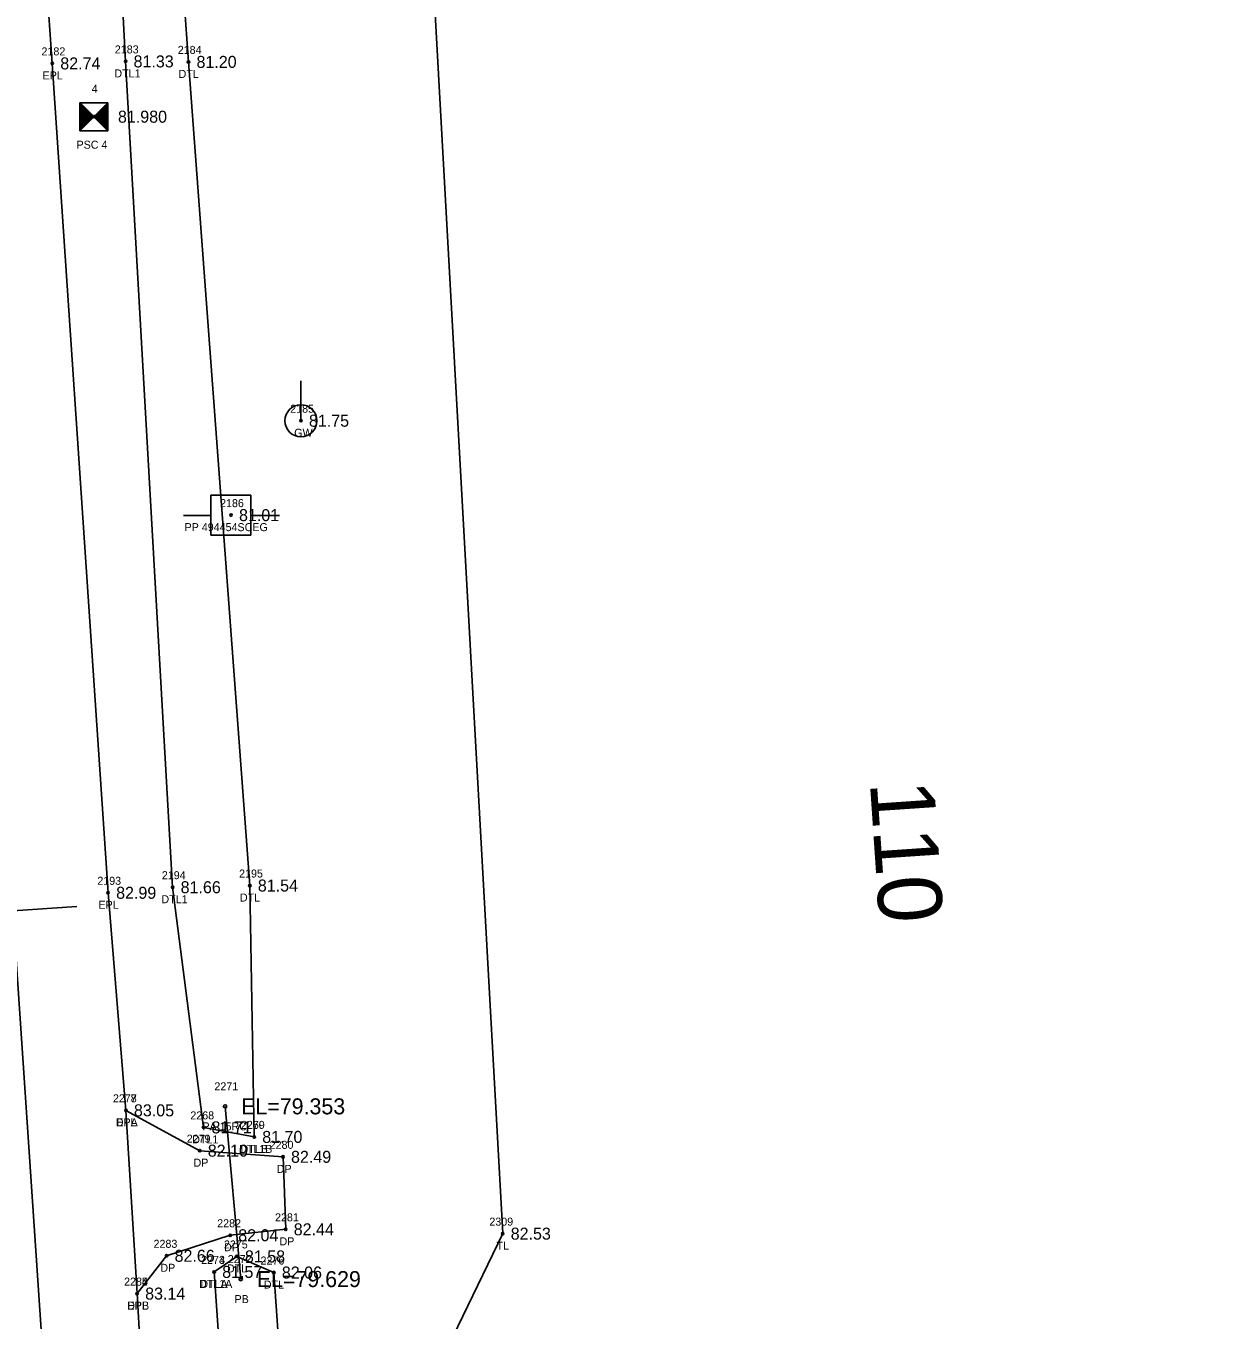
# Model space of a CAD drawing. Extents: x 2139392 to 2143384, y 505395 to 510520.
# Drawn here: x 2140601.5 to 2140750.5, y 507174.1 to 507335.9 of the extents above; entities that cross this region are included whole.
import ezdxf

# ---------------------------------------------------------------- set-up
doc = ezdxf.new("R2010")
doc.units = 0
for name, color, linetype in [('RD_EX_DR_Pipe', 7, 'Continuous'), ('RD_EX_DR_Pipe_txCode', 7, 'Continuous'), ('RD_EX_Driveway', 7, 'Continuous'), ('RD_EX_Driveway_txCode', 7, 'Continuous'), ('RD_EX_H2O', 7, 'Continuous'), ('RD_EX_H2O_txCode', 7, 'Continuous'), ('RD_EX_Road', 7, 'Continuous'), ('RD_EX_Road_txCode', 7, 'Continuous'), ('RD_EX_TX_Driveway_ELEV', 7, 'Continuous'), ('RD_EX_TX_H2O_ELEV', 7, 'Continuous'), ('RD_EX_TX_Road_ELEV', 7, 'Continuous'), ('RD_EX_TX_UT_ELEV', 7, 'Continuous'), ('RD_EX_TX_VEG_ELEV', 7, 'Continuous'), ('RD_EX_UT', 7, 'Continuous'), ('RD_EX_UT_txCode', 7, 'Continuous'), ('RD_EX_VEG', 7, 'Continuous'), ('RD_EX_VEG_txCode', 7, 'Continuous'), ('RD_HC_Cl', 7, 'Continuous'), ('RD_HC_Data_Tic', 7, 'Continuous'), ('RD_HC_Survey', 7, 'Continuous'), ('RD_HC_Survey_ELEV', 7, 'Continuous'), ('RD_HC_TX_Sta50', 7, 'Continuous'), ('RD_HC_txCode', 7, 'Continuous'), ('RD_SMD_Locator', 7, 'Continuous'), ('RD_TX_Pipe_ElevEX', 7, 'Continuous')]:
    doc.layers.add(name, color=color, linetype=linetype)

msp = doc.modelspace()

# ---------------------------------------------------------------- linework, layer by layer
at = {"layer": 'RD_EX_DR_Pipe'}
msp.add_line((2140626.44, 507200.86), (2140628.4, 507179.27), dxfattribs=at)
at = {"layer": 'RD_EX_Driveway'}
msp.add_lwpolyline([(2140614.04, 507200.36), (2140623.27, 507195.32), (2140633.68, 507194.55), (2140634.02, 507185.49), (2140627.08, 507184.75), (2140619.12, 507182.18), (2140615.44, 507177.46)], dxfattribs=at)
at = {"layer": 'RD_EX_H2O'}
msp.add_line((2140625.07, 507180.17), (2140625.92, 507167.91), dxfattribs=at)
for points in [[(2140603.99, 507551.21), (2140601.87, 507547.52), (2140605.21, 507495.06), (2140608.3, 507440.3), (2140613.99, 507331.46), (2140619.88, 507228.25), (2140623.74, 507198.23), (2140630.08, 507197.04)], [(2140603.99, 507551.21), (2140608.04, 507548.03), (2140611.33, 507495.05), (2140614.04, 507440.89), (2140621.86, 507331.4), (2140629.53, 507228.46), (2140630.08, 507197.04)], [(2140625.07, 507180.17), (2140627.92, 507182.1), (2140632.53, 507180.09), (2140633.39, 507167.5), (2140629.4, 507165.09), (2140625.92, 507167.91)]]:
    msp.add_lwpolyline(points, dxfattribs=at)
at = {"layer": 'RD_EX_Road'}
msp.add_lwpolyline([(2140583.43, 507730.59), (2140583.94, 507673.5), (2140583.85, 507666.58), (2140586.13, 507612.82), (2140586.39, 507606.18), (2140590.25, 507541.6), (2140593.48, 507494.33), (2140597.22, 507439.46), (2140604.83, 507331.21), (2140611.81, 507227.55), (2140614.04, 507200.36), (2140615.44, 507177.46), (2140615.82, 507170.81), (2140617.54, 507144.2), (2140618.8, 507126.38), (2140619.22, 507121.84), (2140620.89, 507096.21), (2140626.38, 507013.96)], dxfattribs=at)
at = {"layer": 'RD_EX_UT'}
for p, q in [((2140635.92, 507286.55), (2140635.92, 507291.55)), ((2140629.67, 507277.25), (2140624.67, 507277.25)), ((2140624.67, 507277.25), (2140624.67, 507272.25)), ((2140629.67, 507272.25), (2140629.67, 507277.25)), ((2140621.24, 507274.69), (2140624.71, 507274.69)), ((2140629.6, 507274.69), (2140633.24, 507274.69)), ((2140624.67, 507272.25), (2140629.67, 507272.25))]:
    msp.add_line(p, q, dxfattribs=at)
msp.add_circle((2140635.92, 507286.55), 2, dxfattribs=at)
at = {"layer": 'RD_EX_VEG'}
msp.add_lwpolyline([(2140701.46, 507529.17), (2140641.02, 507547.61), (2140661.15, 507184.95), (2140652.41, 507166.87), (2140661.6, 507156.19), (2140726.62, 507140.25), (2140736.68, 507079.23), (2140750.48, 507072.39)], dxfattribs=at)
at = {"layer": 'RD_HC_Cl'}
msp.add_line((2140574.74, 507595.12), (2140664.08, 506281.81), dxfattribs=at)
at = {"layer": 'RD_HC_Data_Tic'}
msp.add_line((2140599.9, 507225.31), (2140607.88, 507225.85), dxfattribs=at)
at = {"layer": 'RD_HC_Survey'}
for p, q in [((2140608.29, 507326.3), (2140611.79, 507322.8)), ((2140611.79, 507326.3), (2140608.29, 507322.8)), ((2140608.31, 507326.28), (2140608.31, 507322.83)), ((2140608.34, 507326.25), (2140608.34, 507322.85)), ((2140608.36, 507326.23), (2140608.36, 507322.88)), ((2140608.39, 507326.2), (2140608.39, 507322.9)), ((2140608.41, 507326.18), (2140608.41, 507322.93)), ((2140608.43, 507326.15), (2140608.43, 507322.95)), ((2140608.46, 507326.13), (2140608.46, 507322.97)), ((2140608.48, 507326.1), (2140608.48, 507323)), ((2140608.51, 507326.08), (2140608.51, 507323.02)), ((2140608.53, 507326.05), (2140608.53, 507323.05)), ((2140608.56, 507326.03), (2140608.56, 507323.07)), ((2140608.58, 507326), (2140608.58, 507323.1)), ((2140608.61, 507325.98), (2140608.61, 507323.12)), ((2140608.63, 507325.96), (2140608.63, 507323.15)), ((2140608.66, 507325.93), (2140608.66, 507323.17)), ((2140608.68, 507325.91), (2140608.68, 507323.2)), ((2140608.71, 507325.88), (2140608.71, 507323.22)), ((2140608.73, 507325.86), (2140608.73, 507323.25)), ((2140608.76, 507325.83), (2140608.76, 507323.27)), ((2140608.78, 507325.81), (2140608.78, 507323.3)), ((2140608.81, 507325.78), (2140608.81, 507323.32)), ((2140608.83, 507325.76), (2140608.83, 507323.35)), ((2140608.86, 507325.73), (2140608.86, 507323.37)), ((2140608.88, 507325.71), (2140608.88, 507323.4)), ((2140608.91, 507325.68), (2140608.91, 507323.42)), ((2140608.93, 507325.66), (2140608.93, 507323.45)), ((2140608.95, 507325.63), (2140608.95, 507323.47)), ((2140608.98, 507325.61), (2140608.98, 507323.49)), ((2140609, 507325.58), (2140609, 507323.52)), ((2140609.03, 507325.56), (2140609.03, 507323.54)), ((2140609.05, 507325.53), (2140609.05, 507323.57)), ((2140609.08, 507325.51), (2140609.08, 507323.59)), ((2140609.1, 507325.48), (2140609.1, 507323.62)), ((2140609.13, 507325.46), (2140609.13, 507323.64)), ((2140609.15, 507325.44), (2140609.15, 507323.67)), ((2140609.18, 507325.41), (2140609.18, 507323.69)), ((2140609.2, 507325.39), (2140609.2, 507323.72)), ((2140609.23, 507325.36), (2140609.23, 507323.74)), ((2140609.25, 507325.34), (2140609.25, 507323.77)), ((2140609.28, 507325.31), (2140609.28, 507323.79)), ((2140609.3, 507325.29), (2140609.3, 507323.82)), ((2140609.33, 507325.26), (2140609.33, 507323.84)), ((2140609.35, 507325.24), (2140609.35, 507323.87)), ((2140609.38, 507325.21), (2140609.38, 507323.89)), ((2140609.4, 507325.19), (2140609.4, 507323.92)), ((2140609.42, 507325.16), (2140609.42, 507323.94)), ((2140609.45, 507325.14), (2140609.45, 507323.96)), ((2140609.47, 507325.11), (2140609.47, 507323.99)), ((2140609.5, 507325.09), (2140609.5, 507324.01)), ((2140609.52, 507325.06), (2140609.52, 507324.04)), ((2140609.55, 507325.04), (2140609.55, 507324.06)), ((2140609.57, 507325.01), (2140609.57, 507324.09)), ((2140609.6, 507324.99), (2140609.6, 507324.11)), ((2140609.62, 507324.97), (2140609.62, 507324.14)), ((2140609.65, 507324.94), (2140609.65, 507324.16)), ((2140609.67, 507324.92), (2140609.67, 507324.19)), ((2140609.7, 507324.89), (2140609.7, 507324.21)), ((2140609.72, 507324.87), (2140609.72, 507324.24)), ((2140610.35, 507324.87), (2140610.35, 507324.24)), ((2140610.38, 507324.89), (2140610.38, 507324.21)), ((2140610.4, 507324.92), (2140610.4, 507324.19)), ((2140610.43, 507324.94), (2140610.43, 507324.16)), ((2140610.45, 507324.97), (2140610.45, 507324.14)), ((2140610.47, 507324.99), (2140610.47, 507324.11)), ((2140610.5, 507325.01), (2140610.5, 507324.09)), ((2140610.52, 507325.04), (2140610.52, 507324.06)), ((2140610.55, 507325.06), (2140610.55, 507324.04)), ((2140610.57, 507325.09), (2140610.57, 507324.01)), ((2140610.6, 507325.11), (2140610.6, 507323.99)), ((2140610.62, 507325.14), (2140610.62, 507323.96)), ((2140610.65, 507325.16), (2140610.65, 507323.94)), ((2140610.67, 507325.19), (2140610.67, 507323.92)), ((2140610.7, 507325.21), (2140610.7, 507323.89)), ((2140610.72, 507325.24), (2140610.72, 507323.87)), ((2140610.75, 507325.26), (2140610.75, 507323.84)), ((2140610.77, 507325.29), (2140610.77, 507323.82)), ((2140610.8, 507325.31), (2140610.8, 507323.79)), ((2140610.82, 507325.34), (2140610.82, 507323.77)), ((2140610.85, 507325.36), (2140610.85, 507323.74)), ((2140610.87, 507325.39), (2140610.87, 507323.72)), ((2140610.9, 507325.41), (2140610.9, 507323.69)), ((2140610.92, 507325.44), (2140610.92, 507323.67)), ((2140610.95, 507325.46), (2140610.95, 507323.64)), ((2140610.97, 507325.48), (2140610.97, 507323.62)), ((2140610.99, 507325.51), (2140610.99, 507323.59)), ((2140611.02, 507325.53), (2140611.02, 507323.57)), ((2140611.04, 507325.56), (2140611.04, 507323.54)), ((2140611.07, 507325.58), (2140611.07, 507323.52)), ((2140611.09, 507325.61), (2140611.09, 507323.49)), ((2140611.12, 507325.63), (2140611.12, 507323.47)), ((2140611.14, 507325.66), (2140611.14, 507323.45)), ((2140611.17, 507325.68), (2140611.17, 507323.42)), ((2140611.19, 507325.71), (2140611.19, 507323.4)), ((2140611.22, 507325.73), (2140611.22, 507323.37)), ((2140611.24, 507325.76), (2140611.24, 507323.35)), ((2140611.27, 507325.78), (2140611.27, 507323.32)), ((2140611.29, 507325.81), (2140611.29, 507323.3)), ((2140611.32, 507325.83), (2140611.32, 507323.27)), ((2140611.34, 507325.86), (2140611.34, 507323.25)), ((2140611.37, 507325.88), (2140611.37, 507323.22)), ((2140611.39, 507325.91), (2140611.39, 507323.2)), ((2140611.42, 507325.93), (2140611.42, 507323.17)), ((2140611.44, 507325.96), (2140611.44, 507323.15)), ((2140611.46, 507325.98), (2140611.46, 507323.12)), ((2140611.49, 507326), (2140611.49, 507323.1)), ((2140611.51, 507326.03), (2140611.51, 507323.07)), ((2140611.54, 507326.05), (2140611.54, 507323.05)), ((2140611.56, 507326.08), (2140611.56, 507323.02)), ((2140611.59, 507326.1), (2140611.59, 507323)), ((2140611.61, 507326.13), (2140611.61, 507322.97)), ((2140611.64, 507326.15), (2140611.64, 507322.95)), ((2140611.66, 507326.18), (2140611.66, 507322.93)), ((2140611.69, 507326.2), (2140611.69, 507322.9)), ((2140611.71, 507326.23), (2140611.71, 507322.88)), ((2140611.74, 507326.25), (2140611.74, 507322.85)), ((2140611.76, 507326.28), (2140611.76, 507322.83)), ((2140609.75, 507324.84), (2140609.75, 507324.26)), ((2140609.77, 507324.82), (2140609.77, 507324.29)), ((2140609.8, 507324.79), (2140609.8, 507324.31)), ((2140609.82, 507324.77), (2140609.82, 507324.34)), ((2140609.85, 507324.74), (2140609.85, 507324.36)), ((2140609.87, 507324.72), (2140609.87, 507324.39)), ((2140609.9, 507324.69), (2140609.9, 507324.41)), ((2140609.92, 507324.67), (2140609.92, 507324.44)), ((2140609.94, 507324.64), (2140609.94, 507324.46)), ((2140609.97, 507324.62), (2140609.97, 507324.48)), ((2140609.99, 507324.59), (2140609.99, 507324.51)), ((2140610.02, 507324.57), (2140610.02, 507324.53)), ((2140610.05, 507324.57), (2140610.05, 507324.53)), ((2140610.08, 507324.59), (2140610.08, 507324.51)), ((2140610.1, 507324.62), (2140610.1, 507324.48)), ((2140610.13, 507324.64), (2140610.13, 507324.46)), ((2140610.15, 507324.67), (2140610.15, 507324.44)), ((2140610.18, 507324.69), (2140610.18, 507324.41)), ((2140610.2, 507324.72), (2140610.2, 507324.39)), ((2140610.23, 507324.74), (2140610.23, 507324.36)), ((2140610.25, 507324.77), (2140610.25, 507324.34)), ((2140610.28, 507324.79), (2140610.28, 507324.31)), ((2140610.3, 507324.82), (2140610.3, 507324.29)), ((2140610.33, 507324.84), (2140610.33, 507324.26))]:
    msp.add_line(p, q, dxfattribs=at)
msp.add_lwpolyline([(2140611.79, 507326.3), (2140608.29, 507326.3), (2140608.29, 507322.8), (2140611.79, 507322.8)], close=True, dxfattribs=at)
at = {"layer": 'RD_SMD_Locator'}
for centre, radius in [((2140604.83, 507331.21), 0.15), ((2140613.99, 507331.46), 0.15), ((2140621.86, 507331.4), 0.15), ((2140610.04, 507324.55), 0.15), ((2140635.92, 507286.55), 0.15), ((2140627.18, 507274.75), 0.15), ((2140619.88, 507228.25), 0.15), ((2140629.53, 507228.46), 0.15), ((2140611.81, 507227.55), 0.15), ((2140614.04, 507200.36), 0.15), ((2140614.04, 507200.36), 0.15), ((2140626.44, 507200.86), 0.2), ((2140623.74, 507198.23), 0.15), ((2140630.08, 507197.04), 0.15), ((2140630.08, 507197.04), 0.15), ((2140623.27, 507195.32), 0.15), ((2140633.68, 507194.55), 0.15), ((2140627.08, 507184.75), 0.15), ((2140634.02, 507185.49), 0.15), ((2140661.15, 507184.95), 0.15), ((2140619.12, 507182.18), 0.15), ((2140627.92, 507182.1), 0.15), ((2140625.07, 507180.17), 0.15), ((2140625.07, 507180.17), 0.15), ((2140628.4, 507179.27), 0.2), ((2140632.53, 507180.09), 0.15), ((2140615.44, 507177.46), 0.15), ((2140615.44, 507177.46), 0.15)]:
    msp.add_circle(centre, radius, dxfattribs=at)

# ---------------------------------------------------------------- texts
at = {"layer": 'RD_EX_DR_Pipe_txCode'}
for s, p in [('2271', (2140625.1, 507202.86)), ('PA 15RC', (2140623.6, 507197.86)), ('2272', (2140626.77, 507181.27)), ('PB', (2140627.62, 507176.27))]:
    msp.add_text(s, height=1, dxfattribs=at).set_placement(p)
at = {"layer": 'RD_EX_Driveway_txCode'}
for s, p in [('2278', (2140612.41, 507201.36)), ('DPA', (2140612.77, 507198.36)), ('2279', (2140621.64, 507196.32)), ('2280', (2140632.01, 507195.55)), ('DP', (2140622.49, 507193.32)), ('DP', (2140632.9, 507192.55)), ('2281', (2140632.68, 507186.49)), ('2282', (2140625.45, 507185.75)), ('2283', (2140617.49, 507183.18)), ('DP', (2140633.24, 507183.49)), ('DP', (2140626.3, 507182.75)), ('DP', (2140618.34, 507180.18)), ('2284', (2140613.81, 507178.46)), ('DPB', (2140614.19, 507175.46))]:
    msp.add_text(s, height=1, dxfattribs=at).set_placement(p)
at = {"layer": 'RD_EX_H2O_txCode'}
for s, p in [('2183', (2140612.65, 507332.46)), ('2184', (2140620.52, 507332.4)), ('DTL1', (2140612.59, 507329.46)), ('DTL', (2140620.62, 507329.4)), ('2194', (2140618.53, 507229.25)), ('2195', (2140628.19, 507229.46)), ('DTL1', (2140618.47, 507226.25)), ('DTL', (2140628.29, 507226.46)), ('2268', (2140622.09, 507199.23)), ('2270', (2140628.41, 507198.04)), ('2269', (2140628.42, 507198.04)), ('DTL1', (2140622.33, 507196.23)), ('DTL1B', (2140628.19, 507195.04)), ('DTLB', (2140628.36, 507195.04)), ('2275', (2140626.29, 507183.1)), ('2273', (2140623.44, 507181.17)), ('2274', (2140623.44, 507181.17)), ('DTL', (2140626.67, 507180.1)), ('2276', (2140630.87, 507181.09)), ('DTL1A', (2140623.17, 507178.17)), ('DTLA', (2140623.34, 507178.17)), ('DTL', (2140631.28, 507178.09))]:
    msp.add_text(s, height=1, dxfattribs=at).set_placement(p)
at = {"layer": 'RD_EX_Road_txCode'}
for s, p in [('2182', (2140603.48, 507332.21)), ('EPL', (2140603.62, 507329.21)), ('2193', (2140610.46, 507228.55)), ('EPL', (2140610.6, 507225.55)), ('2277', (2140612.41, 507201.36)), ('EPL', (2140612.84, 507198.36)), ('2285', (2140613.81, 507178.46)), ('EPL', (2140614.23, 507175.46))]:
    msp.add_text(s, height=1, dxfattribs=at).set_placement(p)
at = {"layer": 'RD_EX_TX_Driveway_ELEV'}
for s, p in [('83.05', (2140615.04, 507199.61)), ('82.10', (2140624.27, 507194.57)), ('82.49', (2140634.68, 507193.8)), ('82.44', (2140635.02, 507184.74)), ('82.04', (2140628.08, 507184)), ('82.66', (2140620.12, 507181.43)), ('83.14', (2140616.44, 507176.71))]:
    msp.add_text(s, height=1.5, dxfattribs=at).set_placement(p)
at = {"layer": 'RD_EX_TX_H2O_ELEV'}
for s, p in [('81.33', (2140614.99, 507330.71)), ('81.20', (2140622.86, 507330.65)), ('81.66', (2140620.88, 507227.5)), ('81.54', (2140630.53, 507227.71)), ('81.71', (2140624.74, 507197.48)), ('81.70', (2140631.08, 507196.29)), ('81.70', (2140631.08, 507196.29)), ('81.58', (2140628.92, 507181.35)), ('81.57', (2140626.07, 507179.42)), ('81.57', (2140626.07, 507179.42)), ('82.06', (2140633.53, 507179.34))]:
    msp.add_text(s, height=1.5, dxfattribs=at).set_placement(p)
at = {"layer": 'RD_EX_TX_Road_ELEV'}
for s, p in [('82.74', (2140605.83, 507330.46)), ('82.99', (2140612.81, 507226.8)), ('83.05', (2140615.04, 507199.61)), ('83.14', (2140616.44, 507176.71))]:
    msp.add_text(s, height=1.5, dxfattribs=at).set_placement(p)
at = {"layer": 'RD_EX_TX_UT_ELEV'}
msp.add_text('81.75', height=1.5, dxfattribs=at).set_placement((2140636.92, 507285.8))
at = {"layer": 'RD_EX_TX_VEG_ELEV'}
msp.add_text('82.53', height=1.5, dxfattribs=at).set_placement((2140662.15, 507184.2))
at = {"layer": 'RD_EX_UT_txCode'}
for s, p in [('2185', (2140634.58, 507287.55)), ('GW', (2140635.08, 507284.55)), ('2186', (2140625.81, 507275.75)), ('PP 494454SCEG', (2140621.37, 507272.75))]:
    msp.add_text(s, height=1, dxfattribs=at).set_placement(p)
at = {"layer": 'RD_EX_VEG_txCode'}
for s, p in [('2309', (2140659.48, 507185.95)), ('TL', (2140660.37, 507182.95))]:
    msp.add_text(s, height=1, dxfattribs=at).set_placement(p)
at = {"layer": 'RD_HC_Survey_ELEV'}
for s, p in [('81.980', (2140613.04, 507323.8)), ('81.01', (2140628.18, 507274))]:
    msp.add_text(s, height=1.5, dxfattribs=at).set_placement(p)
at = {"layer": 'RD_HC_TX_Sta50'}
msp.add_text('110', height=8, rotation=273.8915, dxfattribs=at).set_placement((2140707.06, 507241.35))
at = {"layer": 'RD_HC_txCode'}
for s, p in [('4', (2140609.75, 507327.55)), ('PSC 4', (2140607.86, 507320.55))]:
    msp.add_text(s, height=1, dxfattribs=at).set_placement(p)
at = {"layer": 'RD_TX_Pipe_ElevEX'}
for s, p in [('EL=79.353', (2140628.44, 507199.86)), ('EL=79.629', (2140630.4, 507178.27))]:
    msp.add_text(s, height=2, dxfattribs=at).set_placement(p)

doc.saveas('drawing.dxf')
